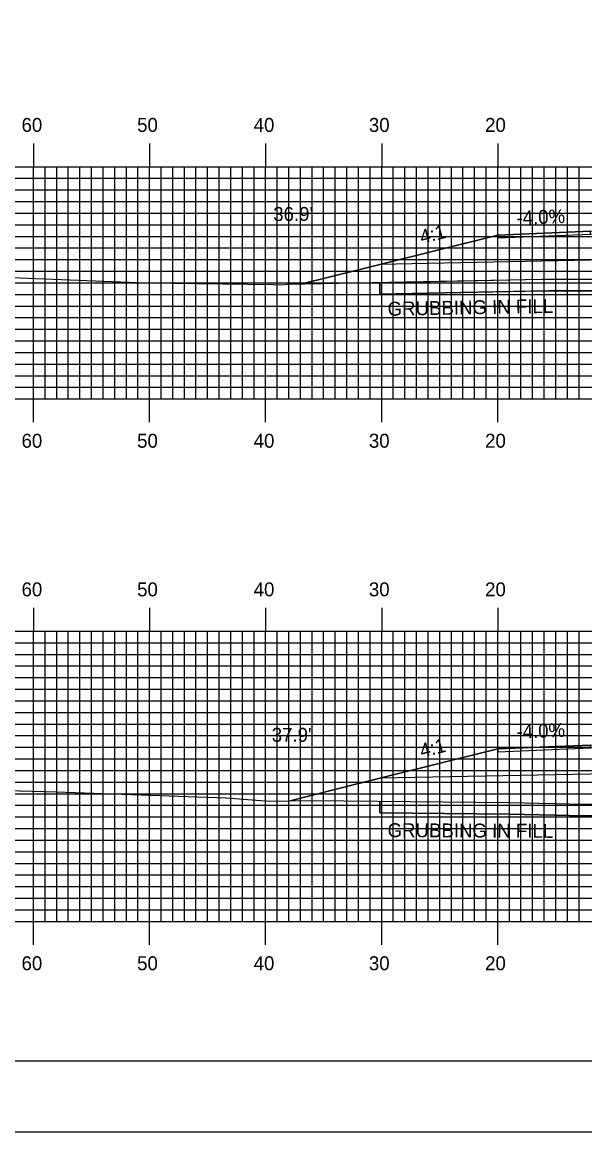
# Model space of a CAD drawing. Extents: x 1774383 to 1774727, y 442591 to 442811.
# Drawn here: x 1774488.2 to 1774536.7, y 442590.5 to 442686.1 of the extents above; entities that cross this region are included whole.
import ezdxf

# ---------------------------------------------------------------- set-up
doc = ezdxf.new("R2010")
doc.units = 0
for name, color, linetype in [('ANNOTATION', 7, 'Continuous'), ('BORDER', 7, 'Continuous'), ('D_Roadway_Centerline', 7, 'Continuous'), ('D_Roadway_Edge_Shoulder', 7, 'Continuous'), ('D_Roadway_SlopeLines', 7, 'Continuous'), ('D_Roadway_SubGrade', 7, 'Continuous'), ('D_Text_Standard', 7, 'Continuous'), ('GRUBBING IN FILL', 7, 'Continuous'), ('H_V ANNOTATION', 7, 'Continuous'), ('MAJOR', 7, 'Continuous'), ('MINOR', 7, 'Continuous'), ('PLOT BOUNDARY', 7, 'Continuous'), ('S_Roadway_Centerline', 7, 'Continuous')]:
    doc.layers.add(name, color=color, linetype=linetype)

msp = doc.modelspace()

# ---------------------------------------------------------------- linework, layer by layer
at = {"layer": 'BORDER'}
msp.add_lwpolyline([(1774399.572, 442596.665), (1774719.572, 442596.665), (1774719.572, 442806.665), (1774399.572, 442806.665)], close=True, dxfattribs=at)
at = {"layer": 'D_Roadway_Centerline'}
for points in [[(1774512.297, 442663.565), (1774517.172, 442664.784), (1774517.278, 442664.811), (1774518.998, 442665.24), (1774523.443, 442666.352), (1774529.172, 442667.784), (1774537.172, 442668.104), (1774549.172, 442668.344), (1774554.507, 442668.238), (1774561.172, 442668.104), (1774563.119, 442668.026), (1774569.172, 442667.784), (1774577.691, 442665.654), (1774579.346, 442665.24), (1774585.327, 442663.745)], [(1774511.278, 442619.06), (1774517.172, 442620.534), (1774517.836, 442620.7), (1774518.998, 442620.99), (1774522.93, 442621.973), (1774529.172, 442623.534), (1774537.172, 442623.854), (1774549.172, 442624.094), (1774561.173, 442623.854), (1774569.172, 442623.534), (1774579.346, 442620.99), (1774585.953, 442619.339), (1774590.971, 442618.084)]]:
    msp.add_lwpolyline(points, dxfattribs=at)
at = {"layer": 'D_Roadway_Edge_Shoulder'}
for points in [[(1774537.172, 442668.104), (1774529.172, 442667.784), (1774529.172, 442667.534), (1774537.172, 442667.854)], [(1774537.172, 442623.854), (1774529.172, 442623.534), (1774529.172, 442623.284), (1774537.172, 442623.604)]]:
    msp.add_lwpolyline(points, close=True, dxfattribs=at)
at = {"layer": 'D_Roadway_SlopeLines'}
for points in [[(1774529.172, 442667.784), (1774518.998, 442665.24), (1774517.172, 442664.784), (1774512.297, 442663.565)], [(1774529.172, 442623.534), (1774518.998, 442620.99), (1774517.172, 442620.534), (1774511.278, 442619.06)]]:
    msp.add_lwpolyline(points, dxfattribs=at)
at = {"layer": 'D_Roadway_SubGrade'}
for points in [[(1774537.172, 442665.604), (1774518.998, 442665.24), (1774529.172, 442667.784), (1774529.172, 442667.534), (1774537.172, 442667.854), (1774549.172, 442668.094), (1774561.172, 442667.854), (1774569.172, 442667.534), (1774569.172, 442667.784), (1774579.346, 442665.24), (1774561.172, 442665.604), (1774549.172, 442665.844)], [(1774537.172, 442621.354), (1774518.998, 442620.99), (1774529.172, 442623.534), (1774529.172, 442623.284), (1774537.172, 442623.604), (1774549.172, 442623.844), (1774561.173, 442623.604), (1774569.172, 442623.284), (1774569.172, 442623.534), (1774579.346, 442620.99), (1774561.173, 442621.354), (1774549.172, 442621.594)]]:
    msp.add_lwpolyline(points, close=True, dxfattribs=at)
at = {"layer": 'GRUBBING IN FILL'}
for p, q in [((1774518.998, 442663.701), (1774518.998, 442662.701)), ((1774518.998, 442663.701), (1774518.998, 442662.701)), ((1774518.998, 442619.027), (1774518.998, 442618.026)), ((1774518.998, 442619.027), (1774518.998, 442618.026))]:
    msp.add_line(p, q, dxfattribs=at)
for points in [[(1774518.998, 442663.701), (1774522.021, 442663.762), (1774532.978, 442663.985), (1774539.889, 442663.982), (1774546.228, 442663.979), (1774549.172, 442663.793), (1774549.172, 442662.791), (1774546.196, 442662.979), (1774539.876, 442662.982), (1774533.555, 442662.984), (1774525.99, 442662.843), (1774518.998, 442662.701)], [(1774518.998, 442663.701), (1774522.021, 442663.762), (1774532.978, 442663.985), (1774539.889, 442663.982), (1774546.228, 442663.979), (1774549.172, 442663.793), (1774549.172, 442662.791), (1774546.196, 442662.979), (1774539.876, 442662.982), (1774533.555, 442662.984), (1774525.99, 442662.843), (1774518.998, 442662.701)], [(1774518.998, 442619.027), (1774521.621, 442618.997), (1774530.184, 442618.901), (1774535.375, 442618.788), (1774543.86, 442618.773), (1774549.172, 442618.764), (1774549.172, 442617.764), (1774543.852, 442617.773), (1774535.364, 442617.788), (1774530.168, 442617.901), (1774524.583, 442617.964), (1774518.998, 442618.026)], [(1774518.998, 442619.027), (1774521.621, 442618.997), (1774530.184, 442618.901), (1774535.375, 442618.788), (1774543.86, 442618.773), (1774549.172, 442618.764), (1774549.172, 442617.764), (1774543.852, 442617.773), (1774535.364, 442617.788), (1774530.168, 442617.901), (1774524.583, 442617.964), (1774518.998, 442618.026)]]:
    msp.add_lwpolyline(points, close=True, dxfattribs=at)
for points in [[(1774518.998, 442662.701), (1774532.981, 442662.985), (1774533.233, 442662.981), (1774533.555, 442662.984), (1774546.196, 442662.979), (1774557.104, 442662.29), (1774558.919, 442662.249), (1774579.346, 442662.421)], [(1774518.998, 442662.701), (1774532.981, 442662.985), (1774533.233, 442662.981), (1774533.555, 442662.984), (1774546.196, 442662.979), (1774557.104, 442662.29), (1774558.919, 442662.249), (1774579.346, 442662.421)], [(1774518.998, 442618.026), (1774530.168, 442617.901), (1774535.364, 442617.788), (1774552.34, 442617.759), (1774555.229, 442617.732), (1774558.114, 442617.672), (1774568.003, 442617.449), (1774575.889, 442617.39), (1774578.7, 442617.363), (1774579.346, 442617.348)], [(1774518.998, 442618.026), (1774530.168, 442617.901), (1774535.364, 442617.788), (1774552.34, 442617.759), (1774555.229, 442617.732), (1774558.114, 442617.672), (1774568.003, 442617.449), (1774575.889, 442617.39), (1774578.7, 442617.363), (1774579.346, 442617.348)]]:
    msp.add_lwpolyline(points, dxfattribs=at)
at = {"layer": 'MAJOR'}
for p, q in [((1774489.172, 442675.669), (1774489.172, 442673.665)), ((1774499.172, 442675.669), (1774499.172, 442673.665)), ((1774509.172, 442675.669), (1774509.172, 442673.665)), ((1774519.172, 442675.669), (1774519.172, 442673.665)), ((1774529.172, 442675.669), (1774529.172, 442673.665)), ((1774409.172, 442673.665), (1774689.172, 442673.665)), ((1774409.172, 442673.665), (1774689.172, 442673.665)), ((1774489.172, 442653.665), (1774489.172, 442673.665)), ((1774499.172, 442653.665), (1774499.172, 442673.665)), ((1774509.172, 442653.665), (1774509.172, 442673.665)), ((1774519.172, 442653.665), (1774519.172, 442673.665)), ((1774529.172, 442653.665), (1774529.172, 442673.665)), ((1774409.172, 442668.665), (1774689.172, 442668.665)), ((1774409.172, 442663.665), (1774689.172, 442663.665)), ((1774409.172, 442658.665), (1774689.172, 442658.665)), ((1774409.172, 442653.665), (1774689.172, 442653.665)), ((1774409.172, 442653.665), (1774689.172, 442653.665)), ((1774489.172, 442651.661), (1774489.172, 442653.665)), ((1774499.172, 442651.661), (1774499.172, 442653.665)), ((1774509.172, 442651.661), (1774509.172, 442653.665)), ((1774519.172, 442651.661), (1774519.172, 442653.665)), ((1774529.172, 442651.661), (1774529.172, 442653.665)), ((1774489.172, 442635.669), (1774489.172, 442633.665)), ((1774499.172, 442635.669), (1774499.172, 442633.665)), ((1774509.172, 442635.669), (1774509.172, 442633.665)), ((1774519.172, 442635.669), (1774519.172, 442633.665)), ((1774529.172, 442635.669), (1774529.172, 442633.665)), ((1774409.172, 442633.665), (1774689.172, 442633.665)), ((1774409.172, 442633.665), (1774689.172, 442633.665)), ((1774489.172, 442608.665), (1774489.172, 442633.665)), ((1774499.172, 442608.665), (1774499.172, 442633.665)), ((1774509.172, 442608.665), (1774509.172, 442633.665)), ((1774519.172, 442608.665), (1774519.172, 442633.665)), ((1774529.172, 442608.665), (1774529.172, 442633.665)), ((1774409.172, 442628.665), (1774689.172, 442628.665)), ((1774409.172, 442623.665), (1774689.172, 442623.665)), ((1774409.172, 442618.665), (1774689.172, 442618.665)), ((1774409.172, 442613.665), (1774689.172, 442613.665)), ((1774409.172, 442608.665), (1774689.172, 442608.665)), ((1774409.172, 442608.665), (1774689.172, 442608.665)), ((1774489.172, 442606.661), (1774489.172, 442608.665)), ((1774499.172, 442606.661), (1774499.172, 442608.665)), ((1774509.172, 442606.661), (1774509.172, 442608.665)), ((1774519.172, 442606.661), (1774519.172, 442608.665)), ((1774529.172, 442606.661), (1774529.172, 442608.665))]:
    msp.add_line(p, q, dxfattribs=at)
at = {"layer": 'MINOR'}
for p, q in [((1774490.172, 442653.665), (1774490.172, 442673.665)), ((1774491.172, 442653.665), (1774491.172, 442673.665)), ((1774492.172, 442653.665), (1774492.172, 442673.665)), ((1774493.172, 442653.665), (1774493.172, 442673.665)), ((1774494.172, 442653.665), (1774494.172, 442673.665)), ((1774495.172, 442653.665), (1774495.172, 442673.665)), ((1774496.172, 442653.665), (1774496.172, 442673.665)), ((1774497.172, 442653.665), (1774497.172, 442673.665)), ((1774498.172, 442653.665), (1774498.172, 442673.665)), ((1774500.172, 442653.665), (1774500.172, 442673.665)), ((1774501.172, 442653.665), (1774501.172, 442673.665)), ((1774502.172, 442653.665), (1774502.172, 442673.665)), ((1774503.172, 442653.665), (1774503.172, 442673.665)), ((1774504.172, 442653.665), (1774504.172, 442673.665)), ((1774505.172, 442653.665), (1774505.172, 442673.665)), ((1774506.172, 442653.665), (1774506.172, 442673.665)), ((1774507.172, 442653.665), (1774507.172, 442673.665)), ((1774508.172, 442653.665), (1774508.172, 442673.665)), ((1774510.172, 442653.665), (1774510.172, 442673.665)), ((1774511.172, 442653.665), (1774511.172, 442673.665)), ((1774512.172, 442653.665), (1774512.172, 442673.665)), ((1774513.172, 442653.665), (1774513.172, 442673.665)), ((1774514.172, 442653.665), (1774514.172, 442673.665)), ((1774515.172, 442653.665), (1774515.172, 442673.665)), ((1774516.172, 442653.665), (1774516.172, 442673.665)), ((1774517.172, 442653.665), (1774517.172, 442673.665)), ((1774518.172, 442653.665), (1774518.172, 442673.665)), ((1774520.172, 442653.665), (1774520.172, 442673.665)), ((1774521.172, 442653.665), (1774521.172, 442673.665)), ((1774522.172, 442653.665), (1774522.172, 442673.665)), ((1774523.172, 442653.665), (1774523.172, 442673.665)), ((1774524.172, 442653.665), (1774524.172, 442673.665)), ((1774525.172, 442653.665), (1774525.172, 442673.665)), ((1774526.172, 442653.665), (1774526.172, 442673.665)), ((1774527.172, 442653.665), (1774527.172, 442673.665)), ((1774528.172, 442653.665), (1774528.172, 442673.665)), ((1774530.172, 442653.665), (1774530.172, 442673.665)), ((1774531.172, 442653.665), (1774531.172, 442673.665)), ((1774532.172, 442653.665), (1774532.172, 442673.665)), ((1774533.172, 442653.665), (1774533.172, 442673.665)), ((1774534.172, 442653.665), (1774534.172, 442673.665)), ((1774535.172, 442653.665), (1774535.172, 442673.665)), ((1774536.172, 442653.665), (1774536.172, 442673.665)), ((1774409.172, 442672.665), (1774689.172, 442672.665)), ((1774409.172, 442671.665), (1774689.172, 442671.665)), ((1774409.172, 442670.665), (1774689.172, 442670.665)), ((1774409.172, 442669.665), (1774689.172, 442669.665)), ((1774409.172, 442667.665), (1774689.172, 442667.665)), ((1774409.172, 442666.665), (1774689.172, 442666.665)), ((1774409.172, 442665.665), (1774689.172, 442665.665)), ((1774409.172, 442664.665), (1774689.172, 442664.665)), ((1774409.172, 442662.665), (1774689.172, 442662.665)), ((1774409.172, 442661.665), (1774689.172, 442661.665)), ((1774409.172, 442660.665), (1774689.172, 442660.665)), ((1774409.172, 442659.665), (1774689.172, 442659.665)), ((1774409.172, 442657.665), (1774689.172, 442657.665)), ((1774409.172, 442656.665), (1774689.172, 442656.665)), ((1774409.172, 442655.665), (1774689.172, 442655.665)), ((1774409.172, 442654.665), (1774689.172, 442654.665)), ((1774490.172, 442608.665), (1774490.172, 442633.665)), ((1774491.172, 442608.665), (1774491.172, 442633.665)), ((1774492.172, 442608.665), (1774492.172, 442633.665)), ((1774493.172, 442608.665), (1774493.172, 442633.665)), ((1774494.172, 442608.665), (1774494.172, 442633.665)), ((1774495.172, 442608.665), (1774495.172, 442633.665)), ((1774496.172, 442608.665), (1774496.172, 442633.665)), ((1774497.172, 442608.665), (1774497.172, 442633.665)), ((1774498.172, 442608.665), (1774498.172, 442633.665)), ((1774500.172, 442608.665), (1774500.172, 442633.665)), ((1774501.172, 442608.665), (1774501.172, 442633.665)), ((1774502.172, 442608.665), (1774502.172, 442633.665)), ((1774503.172, 442608.665), (1774503.172, 442633.665)), ((1774504.172, 442608.665), (1774504.172, 442633.665)), ((1774505.172, 442608.665), (1774505.172, 442633.665)), ((1774506.172, 442608.665), (1774506.172, 442633.665)), ((1774507.172, 442608.665), (1774507.172, 442633.665)), ((1774508.172, 442608.665), (1774508.172, 442633.665)), ((1774510.172, 442608.665), (1774510.172, 442633.665)), ((1774511.172, 442608.665), (1774511.172, 442633.665)), ((1774512.172, 442608.665), (1774512.172, 442633.665)), ((1774513.172, 442608.665), (1774513.172, 442633.665)), ((1774514.172, 442608.665), (1774514.172, 442633.665)), ((1774515.172, 442608.665), (1774515.172, 442633.665)), ((1774516.172, 442608.665), (1774516.172, 442633.665)), ((1774517.172, 442608.665), (1774517.172, 442633.665)), ((1774518.172, 442608.665), (1774518.172, 442633.665)), ((1774520.172, 442608.665), (1774520.172, 442633.665)), ((1774521.172, 442608.665), (1774521.172, 442633.665)), ((1774522.172, 442608.665), (1774522.172, 442633.665)), ((1774523.172, 442608.665), (1774523.172, 442633.665)), ((1774524.172, 442608.665), (1774524.172, 442633.665)), ((1774525.172, 442608.665), (1774525.172, 442633.665)), ((1774526.172, 442608.665), (1774526.172, 442633.665)), ((1774527.172, 442608.665), (1774527.172, 442633.665)), ((1774528.172, 442608.665), (1774528.172, 442633.665)), ((1774530.172, 442608.665), (1774530.172, 442633.665)), ((1774531.172, 442608.665), (1774531.172, 442633.665)), ((1774532.172, 442608.665), (1774532.172, 442633.665)), ((1774533.172, 442608.665), (1774533.172, 442633.665)), ((1774534.172, 442608.665), (1774534.172, 442633.665)), ((1774535.172, 442608.665), (1774535.172, 442633.665)), ((1774536.172, 442608.665), (1774536.172, 442633.665)), ((1774409.172, 442632.665), (1774689.172, 442632.665)), ((1774409.172, 442631.665), (1774689.172, 442631.665)), ((1774409.172, 442630.665), (1774689.172, 442630.665)), ((1774409.172, 442629.665), (1774689.172, 442629.665)), ((1774409.172, 442627.665), (1774689.172, 442627.665)), ((1774409.172, 442626.665), (1774689.172, 442626.665)), ((1774409.172, 442625.665), (1774689.172, 442625.665)), ((1774409.172, 442624.665), (1774689.172, 442624.665)), ((1774409.172, 442622.665), (1774689.172, 442622.665)), ((1774409.172, 442621.665), (1774689.172, 442621.665)), ((1774409.172, 442620.665), (1774689.172, 442620.665)), ((1774409.172, 442619.665), (1774689.172, 442619.665)), ((1774409.172, 442617.665), (1774689.172, 442617.665)), ((1774409.172, 442616.665), (1774689.172, 442616.665)), ((1774409.172, 442615.665), (1774689.172, 442615.665)), ((1774409.172, 442614.665), (1774689.172, 442614.665)), ((1774409.172, 442612.665), (1774689.172, 442612.665)), ((1774409.172, 442611.665), (1774689.172, 442611.665)), ((1774409.172, 442610.665), (1774689.172, 442610.665)), ((1774409.172, 442609.665), (1774689.172, 442609.665))]:
    msp.add_line(p, q, dxfattribs=at)
at = {"layer": 'PLOT BOUNDARY'}
msp.add_lwpolyline([(1774383.385, 442590.547), (1774723.385, 442590.547), (1774723.385, 442810.547), (1774383.385, 442810.547)], close=True, dxfattribs=at)
at = {"layer": 'S_Roadway_Centerline'}
for points in [[(1774486.701, 442664.161), (1774489.383, 442664.027), (1774498.897, 442663.651), (1774509.835, 442663.514), (1774510.506, 442663.506), (1774511.065, 442663.54), (1774532.978, 442663.985), (1774533.237, 442663.981), (1774533.551, 442663.984), (1774546.228, 442663.979), (1774557.147, 442663.289), (1774558.926, 442663.249), (1774579.296, 442663.421), (1774581.926, 442663.541), (1774601.548, 442664.721)], [(1774409.172, 442620.913), (1774409.418, 442620.916), (1774422.837, 442621.32), (1774428.202, 442621.497), (1774433.877, 442621.526), (1774445.557, 442621.32), (1774451.225, 442621.215), (1774468.104, 442620.333), (1774474.637, 442620.193), (1774481.884, 442619.911), (1774486.894, 442619.928), (1774491.126, 442619.822), (1774505.753, 442619.321), (1774509.5, 442619.027), (1774513.058, 442619.093), (1774530.184, 442618.901), (1774535.375, 442618.788), (1774552.345, 442618.759), (1774555.244, 442618.732), (1774558.135, 442618.672), (1774568.018, 442618.449), (1774575.898, 442618.39), (1774578.717, 442618.363), (1774600.441, 442617.868)]]:
    msp.add_lwpolyline(points, dxfattribs=at)

# ---------------------------------------------------------------- texts
at = {"layer": 'ANNOTATION'}
for s, rotation, p in [('-4.0%', 2.29053, (1774530.804, 442668.651)), ('4:1', 14.03912, (1774522.621, 442667.008)), ('-4.0%', 2.29086, (1774530.804, 442624.401)), ('4:1', 14.03866, (1774522.621, 442622.758))]:
    msp.add_text(s, height=1.2, rotation=rotation, dxfattribs=at).set_placement(p)
at = {"layer": 'D_Text_Standard'}
for s, p in [("36.9'", (1774509.828, 442668.995)), ("37.9'", (1774509.698, 442624.137))]:
    msp.add_text(s, height=1.2, dxfattribs=at).set_placement(p)
at = {"layer": 'GRUBBING IN FILL'}
for rotation, p in [(1.02028, (1774519.691, 442660.824)), (359.74859, (1774519.677, 442615.926))]:
    msp.add_text('GRUBBING IN FILL', height=1.2, rotation=rotation, dxfattribs=at).set_placement(p)
at = {"layer": 'H_V ANNOTATION'}
for s, p in [('60', (1774488.144, 442676.665)), ('50', (1774498.101, 442676.665)), ('40', (1774508.144, 442676.665)), ('30', (1774518.069, 442676.665)), ('20', (1774528.08, 442676.665)), ('60', (1774488.144, 442649.465)), ('50', (1774498.101, 442649.465)), ('40', (1774508.144, 442649.465)), ('30', (1774518.069, 442649.465)), ('20', (1774528.08, 442649.465)), ('60', (1774488.144, 442636.665)), ('50', (1774498.101, 442636.665)), ('40', (1774508.144, 442636.665)), ('30', (1774518.069, 442636.665)), ('20', (1774528.08, 442636.665)), ('60', (1774488.144, 442604.465)), ('50', (1774498.101, 442604.465)), ('40', (1774508.144, 442604.465)), ('30', (1774518.069, 442604.465)), ('20', (1774528.08, 442604.465))]:
    msp.add_text(s, height=1.2, dxfattribs=at).set_placement(p)

doc.saveas('drawing.dxf')
